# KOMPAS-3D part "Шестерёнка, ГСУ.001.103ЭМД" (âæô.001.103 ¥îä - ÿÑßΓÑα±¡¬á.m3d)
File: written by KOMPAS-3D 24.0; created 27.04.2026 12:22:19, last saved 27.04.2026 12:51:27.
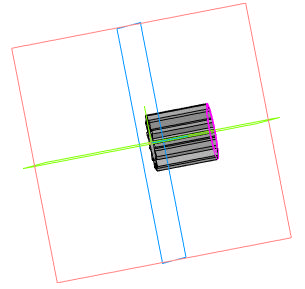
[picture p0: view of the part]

Document properties: Автор: USG_411; Полное имя файла: C:\Users\USG_411.STUD\Desktop\ГМ2704_411-23\Двигатель мясорубки\ГСУ.001.103 ЭМД - Шестерёнка.m3d

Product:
- Part/product: Шестерёнка  | designation ГСУ.001.103ЭМД
    Масса: 0.005595

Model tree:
1. Модель ВиМП
2. Эскиз:2
3. Элемент выдавливания:1
     Расстояние 1 = 13
4. Эскиз:3  (with: Грань.Элемент выдавливания:1, Ребро.Элемент выдавливания:1)
5. Элемент выдавливания:2
     Расстояние 2 = 13
6. Массив по концентрической сетке:1  (with: Элемент выдавливания:2, Эскиз:3, Грань.Элемент выдавливания:1)  (13 pattern instances)
     Шаг 2 = 360
7. Эскиз:4  (with: Грань.Элемент вращения:1, Ребро.Элемент вращения:1)
8. Элемент вращения:2  (with: Грань.Элемент выдавливания:1)
     Угол 1 = 360

Referenced files in C:\Users\USG_411.STUD\Desktop\ГМ2704_411-23\Двигатель мясорубки\: ГСУ.001.100 ЭСБ - Ротор.a3d
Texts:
  ГСУ.001.103
  ГСУ.001.103 ЭМД
  Плоскость XY.Начало координат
